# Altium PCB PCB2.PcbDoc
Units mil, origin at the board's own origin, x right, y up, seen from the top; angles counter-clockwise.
Board outline 3150 x 1775 mil, 2 copper layers (Top Layer, Bottom Layer); 4 components, 4 nets, 14 pads, 0 vias.
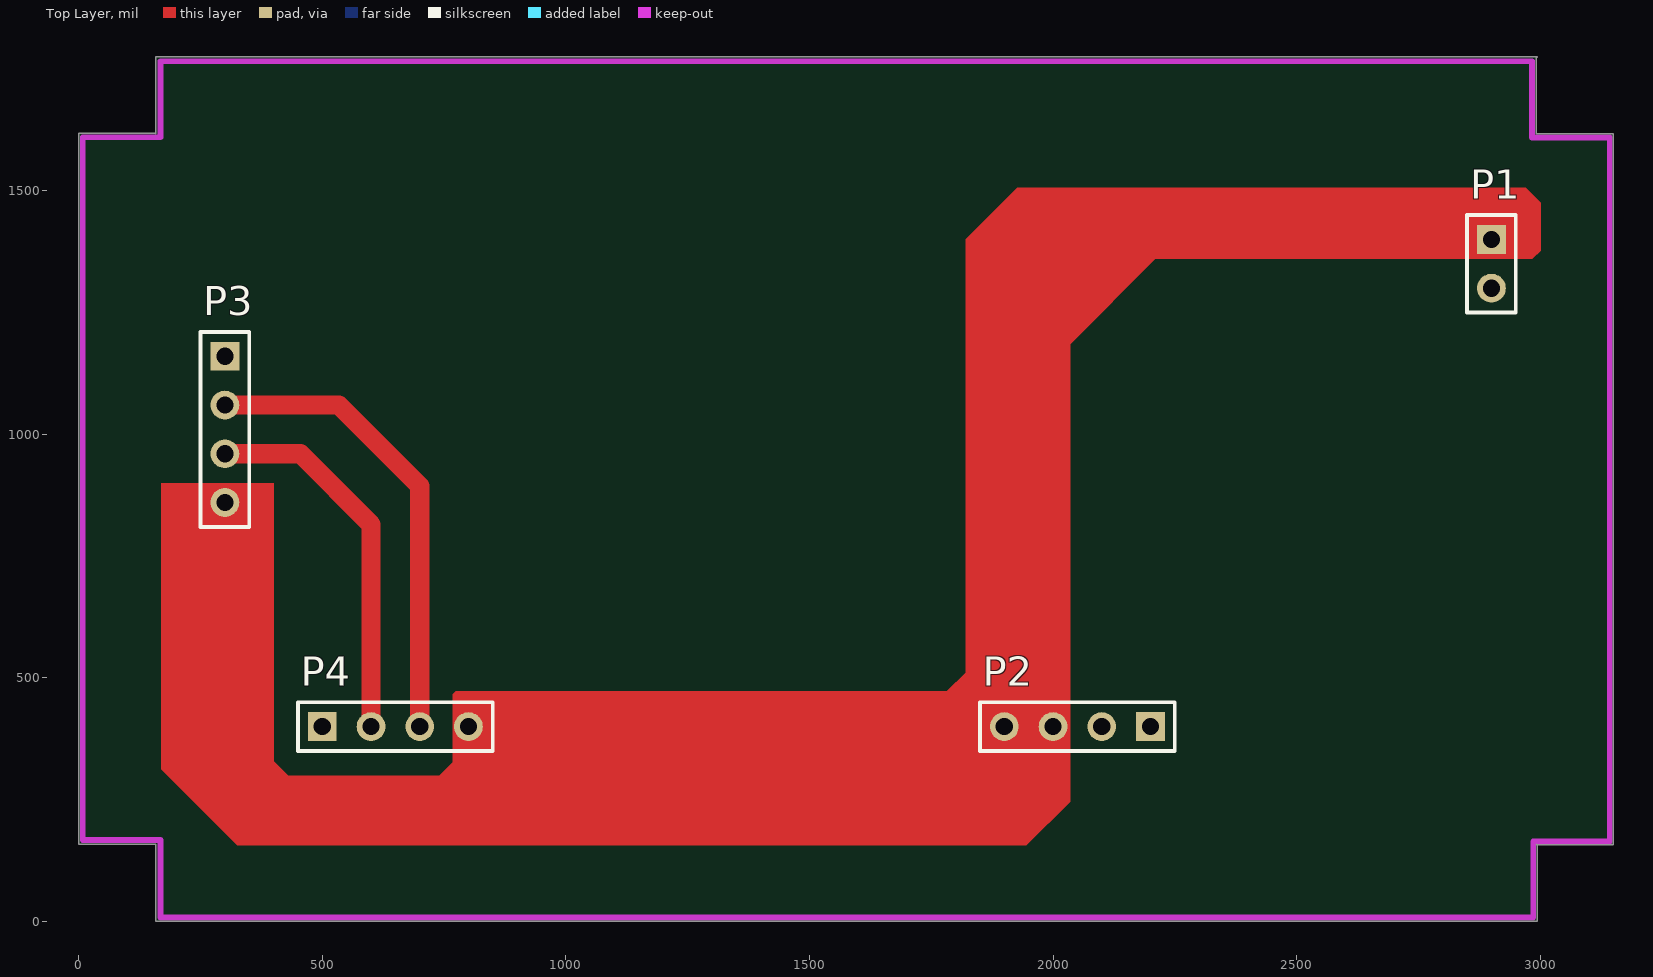
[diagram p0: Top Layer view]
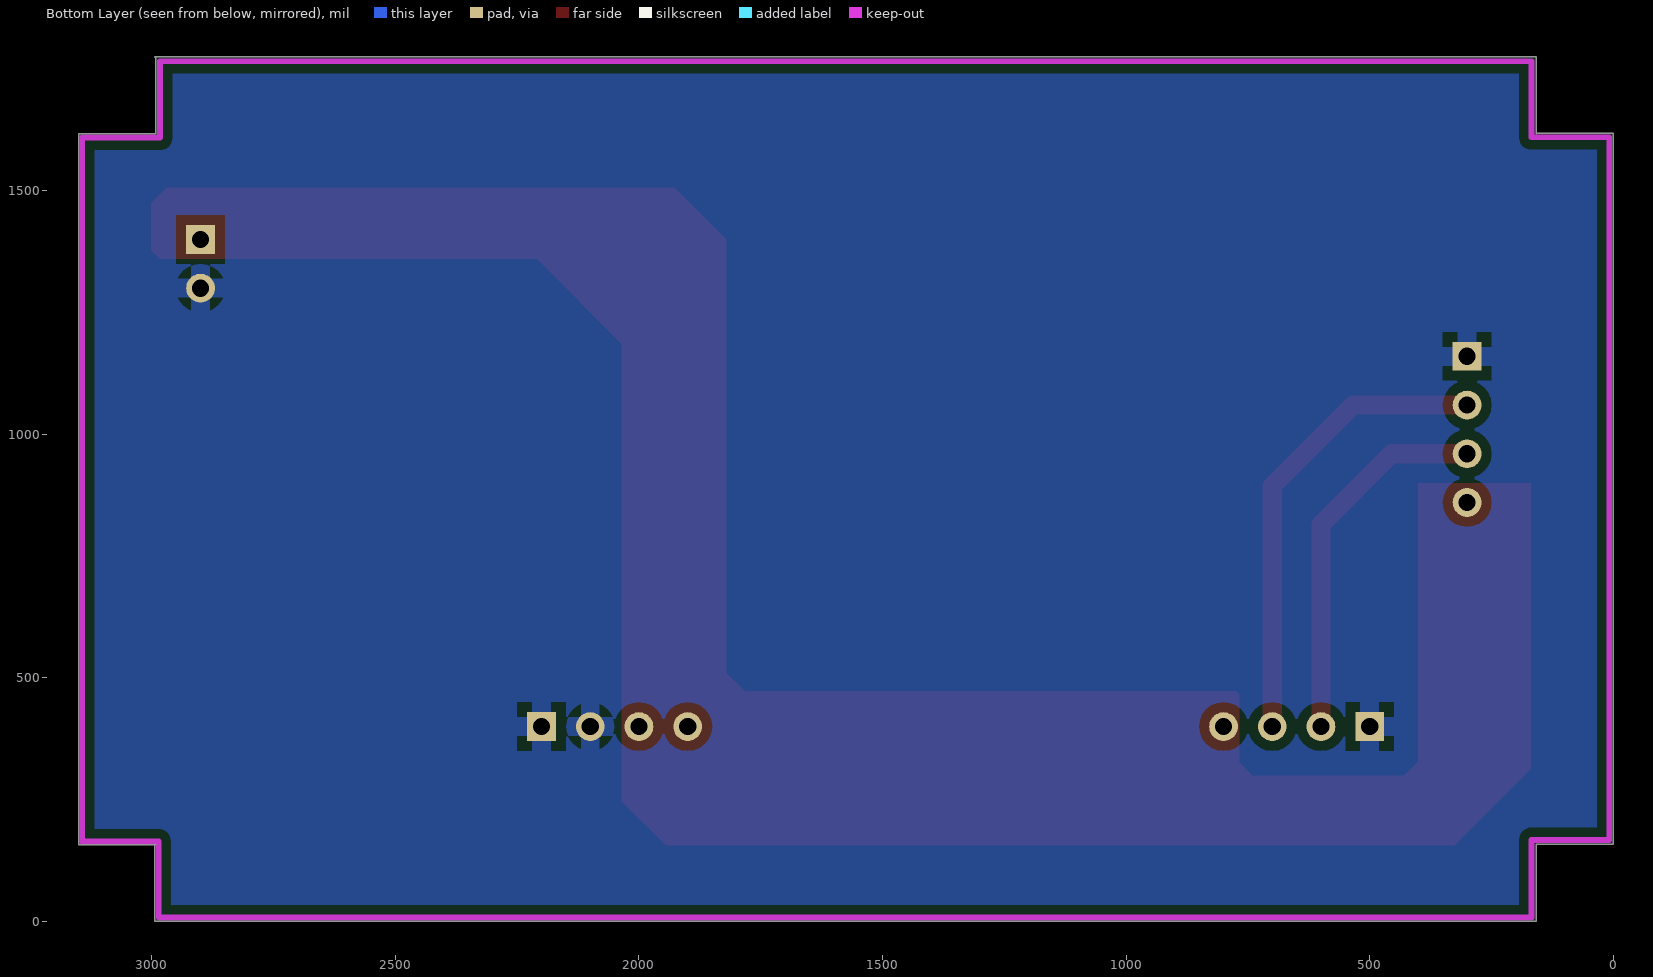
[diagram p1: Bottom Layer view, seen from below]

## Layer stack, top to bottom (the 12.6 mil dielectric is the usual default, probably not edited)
Top Layer: signal copper 1.4
Dielectric: core 12.6, FR-4, Dk 4.8
Bottom Layer: signal copper 1.4

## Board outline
0,1618 157,1618 158,1617 158,1775 2994,1775 2992,1773 2992,1617 3150,1617 3150,157 2993,157 2992,158 2994,156 2994,0 158,0 158,158 0,158 0,1618

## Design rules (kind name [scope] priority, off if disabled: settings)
Clearance [All] p1: gap=20
ComponentClearance [All] p1: gap=10 collisioncheckmode=3 verticalgap=10
PlaneClearance [All] p1: clearance=40
PlaneConnect [All] p1: planeconnectstyle=Relief reliefexpansion=30 reliefentries=4 reliefconductorwidth=30 reliefairgap=20
PolygonConnect [All] p1: connectstyle=Relief reliefconductorwidth=40 reliefentries=4 polygonreliefangle="90 Angle"
RoutingVias [All] p1: holewidth=23.62 width=39.37 viastyle="Through Hole" minholewidth=28 minwidth=50 maxholewidth=28 maxwidth=50
SolderMaskExpansion [All] p1: expansion=4
TestPointUsage [All] p1: valid=0 allowmultiple=FALSE
Testpoint [All] p1: side=15 testpointundercomponent=TRUE minsize=40 maxsize=100 preferedsize=60 minholesize=0 maxholesize=40 preferedholesize=32 testpointgrid=1 style=1023 order=0-112345678
Width [All] p1: maxlimit=39.37 minlimit=39.37 preferedwidth=39.37
16 further rules are at their usual default settings.

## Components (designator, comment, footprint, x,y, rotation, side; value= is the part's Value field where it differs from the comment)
P1 "Header 2" HDR1X2 2900,1400 r270 top
P2 "Header 4" HDR1X4 2200,400 r180 top
P3 "Header 4" HDR1X4 300,1160 r270 top
P4 "Header 4" HDR1X4 500,400 r0 top

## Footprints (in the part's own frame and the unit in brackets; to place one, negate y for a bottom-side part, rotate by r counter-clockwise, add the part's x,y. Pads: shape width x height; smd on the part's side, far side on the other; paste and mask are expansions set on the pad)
HDR1X2 [mm] "Connector; Header; 2 Position"
  rect 1.5x1.5 hole 0.9: 1(0,0)
  round 1.5 hole 0.9: 2(2.54,0)
  silkscreen extent -1.27,-1.27 3.81,1.27
HDR1X4 [mm] "Connector; Header; 4 Position"
  rect 1.5x1.5 hole 0.9: 1(0,0)
  round 1.5 hole 0.9: 2(2.54,0) 3(5.08,0) 4(7.62,0)
  silkscreen extent -1.27,-1.27 8.89,1.27

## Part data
P1: "Header, 2-Pin"
P2 P3 P4: "Header, 4-Pin"

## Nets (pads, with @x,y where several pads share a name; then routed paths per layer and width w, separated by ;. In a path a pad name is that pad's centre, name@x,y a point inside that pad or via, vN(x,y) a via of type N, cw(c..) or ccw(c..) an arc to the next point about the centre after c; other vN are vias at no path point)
GND: P1.2 P2.1 P2.2 P3.1 P4.1
RX1: P3.2 P4.3 | length 966.8
  Top Layer w39.37: P3.2 534,1060 700,894 P4.3@700,396
TX1: P3.3 P4.2 | length 780.1
  Top Layer w39.37: P3.3 455,960 600,815 P4.2@600,395
VCC: P1.1 P2.3 P2.4 P3.4 P4.4 | length 4489.1
  Top Layer w39.37: P3.4 300,347 405,242 1918,242 2000,324 2000,1248 2152,1400 P1.1 ; 796,242 800,246 P4.4 ; 1900,248 P2.4

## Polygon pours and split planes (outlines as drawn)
GND on Bottom Layer "Bottom Layer-No Net" (solid, remove dead copper): 8,1610 167,1610 168,1611 168,1766 2983,1766 2983,1609 3143,1609 3143,164 2986,164 2986,8 168,8 167,9 167,167 8,167 8,1610

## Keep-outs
Keep-Out Layer:
  lines w11.81: 167,167 8,167 8,1610 168,1610 ; 168,167 168,8 2986,8 2986,164 3143,164 3143,1609 2983,1609 2983,1766 168,1766 168,1611

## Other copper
Top Layer:
  region net VCC: 169,900 400,900 400,329 430,299 740,299 768,327 768,466 774,472 1782,472 1821,511 1821,1400 1927,1506 2970,1506 3001,1475 3001,1377 2984,1360 2210,1360 2035,1185 2035,246 1945,156 325,156 169,312

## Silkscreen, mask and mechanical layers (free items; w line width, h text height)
Drill Drawing:
  text ".LEGEND" at 3349.61,200 h60
  text "Drill Drawing." at 3349.61,100 h60

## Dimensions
3143,164 to 2986,4 on Mechanical 1
2983,1766 to 3143,1609 on Mechanical 1
168,8 to 2986,8 on Mechanical 1
8,167 to 8,1610 on Mechanical 1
